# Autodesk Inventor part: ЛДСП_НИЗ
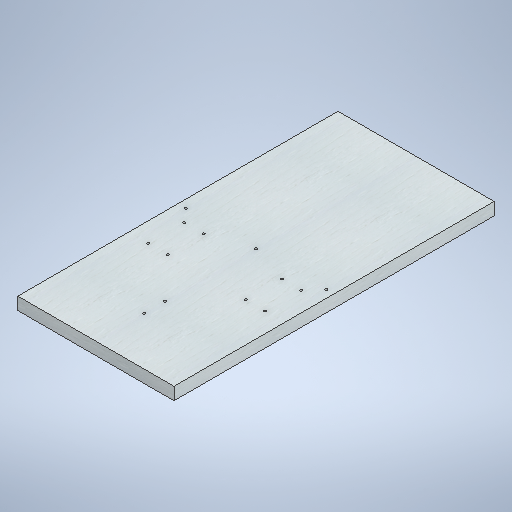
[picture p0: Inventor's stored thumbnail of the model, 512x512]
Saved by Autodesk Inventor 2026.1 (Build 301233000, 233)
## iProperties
Created: 2025-12
Part Number: ЛДСП_НИЗ
Material: Типовые
Document SubType Name: Modeling
Designer: Yury Melnikov
Density: 1 g/cm^3
Appearance: Дерево — окрашенное — белое
Author: Yury Melnikov
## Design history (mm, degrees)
sketch "Эскиз1"
  geometry: L1 (0, 410)-(-200, 410); L2 (-200, 410)-(-200, 0); L3 (-200, 0)-(0, 0); L4 (0, 0)-(0, 410); L5 (0, 205)-(-200, 205); C1 r 1.5 at (-10, 205); C2 r 1.5 at (-100, 205); C3 r 1.5 at (-190, 205); 1 further point
  constraints: 10 end point, 3 centre point, 2 horizontal, 2 midpoint, 2 parallel, 1 coincident, 1 perpendicular, 1 point on line, 4 other
  dimensions: "d0" = 200 distance of L3.end L2.end; "d1" = 410 distance of L2.end L1.end; "d4" = 90 distance of C1.centre C2.centre (derived); "d9" = 3 diameter of C1; "d10" = 10 distance from line of L4 C1.centre; "d11" = 10 distance from line of C3.centre L2
extrude "Выдавливание1" new body sketch "Эскиз1" distance "d12" = 16; taper "d13" = 0 deg
sketch "Эскиз2"
  geometry: L1 (0, -197)-(200, -197); L2 (200, -197)-(200, -213); L3 (200, -213)-(0, -213); L4 (0, -213)-(0, -197); L5 (0, 0)-(0, -410) reference; L6 (200, -410)-(200, 0) reference; L7 (25, -222)-(50, -222); L8 (50, -222)-(50, -268); L9 (50, -268)-(25, -268); L10 (25, -268)-(25, -222); L11 (100, -213)-(100, -235.73); L12 (175, -222)-(150, -222); L13 (175, -268)-(175, -222); L14 (150, -268)-(175, -268); L15 (150, -222)-(150, -268); C1 r 1.5 at (25, -222); C2 r 1.5 at (50, -222); C3 r 1.5 at (25, -268); C4 r 1.5 at (50, -268); C5 r 1.5 at (175, -222); C6 r 1.5 at (150, -222); C7 r 1.5 at (175, -268); C8 r 1.5 at (150, -268); 8 further points
  constraints: 26 end point, 11 symmetric about line, 8 centre point, 8 coincident, 4 parallel, 3 horizontal, 3 midpoint, 2 collinear, 2 perpendicular, 2 vertical, 1 horizontal alignment, 13 other
  dimensions: "d14" = 16 distance of L1.end L2.end; "d15" = 25 distance of L7.start L7.end; "d16" = 46 distance of L7.end L8.end; "d17" = 25 distance between parallel lines of L5 L10; "d18" = 9 distance between parallel lines of L7 L3; "d19" = 3 diameter of C1; "d22" = 25 distance of L7.start point (50, -222); "d25" = 46 distance of L7.start point (25, -268)
extrude "Выдавливание2" cut sketch "Эскиз2" distance "d28" = 15; taper "d29" = 0 deg
sketch "Эскиз3"
  geometry: L1 (0, -197)-(200, -197); L2 (200, -197)-(200, -213); L3 (200, -213)-(0, -213); L4 (0, -213)-(0, -197); L5 (200, -410)-(200, 0) reference; L6 (0, 0)-(0, -410) reference; L7 (0, -410)-(200, -410) reference; C1 r 1.5 at (100, -321.431); C2 r 1.5 at (100, -348); 3 further points
  constraints: 8 end point, 3 midpoint, 2 centre point, 2 collinear, 2 parallel, 2 vertical alignment, 1 coincident, 1 equal radius, 1 horizontal, 1 perpendicular
  dimensions: "d30" = 16 distance of L1.end L2.end; "d31" = 135 distance from line of C2.centre L3; "d32" = 26.569 distance of C2.centre C1.centre; "d33" = 3 diameter of C1
extrude "Выдавливание3" cut sketch "Эскиз3" distance "d34" = 15; taper "d35" = 0 deg
node "Твердое тело1"
node "Эскиз — прямоугольный массив1" dims "d4" = 90 (derived), "d7" = 10
node "Эскиз — прямоугольный массив2" dims "d22" = 25, "d25" = 46
